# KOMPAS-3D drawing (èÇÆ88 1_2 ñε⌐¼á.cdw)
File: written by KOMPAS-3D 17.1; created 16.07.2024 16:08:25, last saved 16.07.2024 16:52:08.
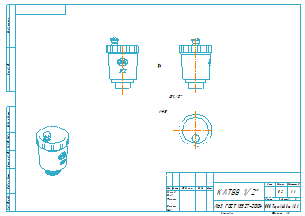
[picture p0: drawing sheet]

Sheet 1: A3, landscape

Title block, sheet 1: name: КАТ88 1/2"; material: Л63  ГОСТ 15527-2004; mass: 0,2; scale: 1:1; sheets: 1; organisation: ООО Торговый дом АДЛ; sheet format: A3; stored path: \\adlc.lan\data\АДЛ_ПКД\3D-модели\ADL production\Клапаны КАТ ГРАНРЕГ\КАТ88\КАТ88 1_2 дюйма.cdw

Views: Спереди 1, Проекционный вид 2, Проекционный вид 4, Изометрия 5
Dimensions and other numbers on the sheet: 1/2"; 70; 45; 1:1; 1; 0,2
